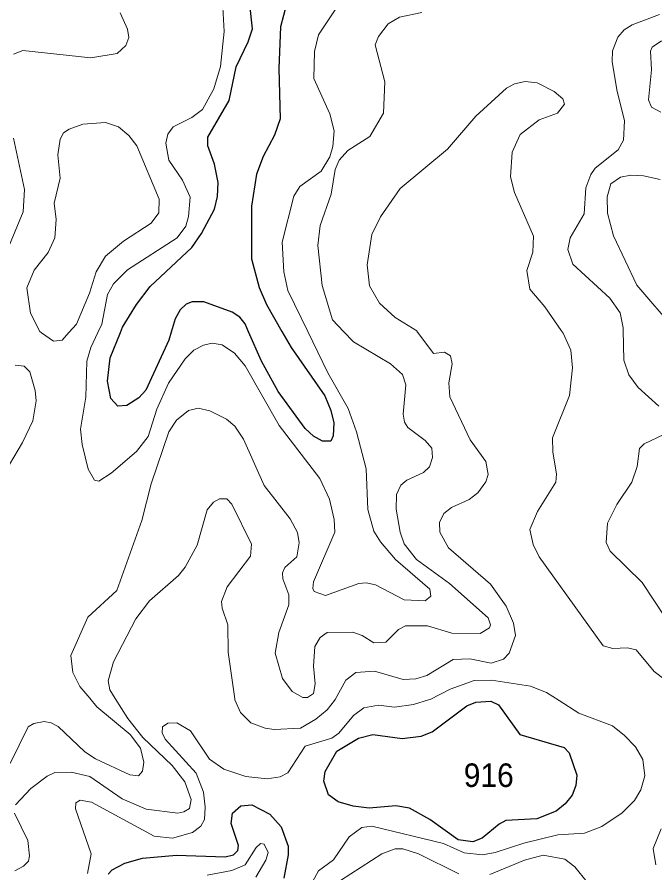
# Model space of a CAD drawing. Extents: x 473.9 to 500, y 7733.1 to 7760.8.
# Drawn here: x 490.401 to 492.567, y 7740.495 to 7743.401 of the extents above; entities that cross this region are included whole.
import ezdxf

# ---------------------------------------------------------------- set-up
doc = ezdxf.new("R2010")
doc.units = 0
doc.header["$LTSCALE"] = 0.032
doc.layers.add('1', color=7, linetype='Continuous', lineweight=25)
doc.layers.add('2', color=7, linetype='Continuous', lineweight=13)
doc.layers.add('21', color=7, linetype='Continuous')

msp = doc.modelspace()

# ---------------------------------------------------------------- linework, layer by layer
at = {"layer": '1'}
for points in [[(491.3263, 7743.4848), (491.2954, 7743.3689), (491.2906, 7743.2268), (491.2949, 7743.0556), (491.2755, 7743.0003), (491.2369, 7742.9279), (491.2146, 7742.8682), (491.1973, 7742.7591), (491.1972, 7742.5807), (491.2232, 7742.483), (491.2488, 7742.4256), (491.3009, 7742.3333), (491.3316, 7742.2789), (491.4465, 7742.1152), (491.467, 7742.0658), (491.477, 7742.0236), (491.4748, 7741.9793), (491.4673, 7741.9618), (491.4385, 7741.9609), (491.4077, 7741.9782), (491.3794, 7742.0048), (491.2881, 7742.1302), (491.2313, 7742.2335), (491.1874, 7742.3328), (491.1756, 7742.3594), (491.1581, 7742.3824), (491.1313, 7742.3998), (491.0358, 7742.4345), (490.996, 7742.4343), (490.976, 7742.4264), (490.9552, 7742.4078), (490.9378, 7742.3763), (490.9244, 7742.3316), (490.9161, 7742.304), (490.8389, 7742.1344), (490.815, 7742.1085), (490.7739, 7742.082), (490.7435, 7742.08), (490.7197, 7742.1057), (490.7086, 7742.1648), (490.7169, 7742.2443), (490.7526, 7742.3308), (490.7597, 7742.348), (490.8064, 7742.4251), (490.8527, 7742.4862), (490.995, 7742.6191), (491.028, 7742.6666), (491.0712, 7742.7494), (491.0822, 7742.7922), (491.0837, 7742.8401), (491.0718, 7742.9016), (491.0494, 7742.9644), (491.0487, 7742.9932), (491.1216, 7743.1186), (491.145, 7743.2324), (491.1862, 7743.317), (491.2005, 7743.3612), (491.1917, 7743.4447)], [(490.7106, 7740.4911), (490.7246, 7740.5056), (490.7669, 7740.5284), (490.8274, 7740.545), (490.9432, 7740.5554), (491.1078, 7740.5499), (491.1357, 7740.556), (491.1508, 7740.5708), (491.1531, 7740.5886), (491.1278, 7740.6627), (491.1331, 7740.6978), (491.1616, 7740.7231), (491.1982, 7740.726), (491.2594, 7740.6941), (491.2981, 7740.6514), (491.3218, 7740.586), (491.3219, 7740.5567), (491.3075, 7740.4772)]]:
    msp.add_lwpolyline(points, dxfattribs=at)
msp.add_lwpolyline([(491.4583, 7740.7605), (491.4433, 7740.8069), (491.4472, 7740.8395), (491.4871, 7740.9086), (491.5606, 7740.9526), (491.6089, 7740.9647), (491.7086, 7740.9511), (491.7741, 7740.9592), (491.8107, 7740.9744), (491.929, 7741.0627), (491.9589, 7741.0754), (492.0098, 7741.0789), (492.0363, 7741.0665), (492.1085, 7740.965), (492.2595, 7740.9206), (492.2766, 7740.9024), (492.3019, 7740.8266), (492.2988, 7740.7924), (492.2862, 7740.7592), (492.2629, 7740.7296), (492.2318, 7740.7046), (492.1669, 7740.6793), (492.0612, 7740.6731), (492.0381, 7740.6609), (491.9811, 7740.6134), (491.9492, 7740.6005), (491.8997, 7740.6079), (491.8031, 7740.6768), (491.7337, 7740.7147), (491.6874, 7740.7227), (491.5968, 7740.7146), (491.5427, 7740.7216), (491.4921, 7740.7362)], close=True, dxfattribs=at)
at = {"layer": '2'}
for points in [[(491.5621, 7741.4778), (491.587, 7741.4808), (491.618, 7741.4739), (491.716, 7741.4226), (491.7869, 7741.4187), (491.8069, 7741.4348), (491.8033, 7741.4582), (491.6862, 7741.5597), (491.6353, 7741.6195), (491.6127, 7741.656), (491.5922, 7741.7288), (491.5867, 7741.8669), (491.5538, 7741.9935), (491.5258, 7742.0723), (491.4563, 7742.1939), (491.3885, 7742.3337), (491.321, 7742.4728), (491.307, 7742.5364), (491.3019, 7742.6374), (491.3408, 7742.7934), (491.3615, 7742.826), (491.434, 7742.8787), (491.4634, 7742.9274), (491.474, 7742.9623), (491.478, 7743.0155), (491.4628, 7743.0724), (491.4095, 7743.1932), (491.411, 7743.2847), (491.4245, 7743.341), (491.5397, 7743.5144)], [(491.0984, 7743.4542), (491.1049, 7743.3529), (491.0917, 7743.2333), (491.0694, 7743.1573), (491.0309, 7743.088), (490.9952, 7743.0602), (490.9311, 7743.0286), (490.9132, 7743.004), (490.9063, 7742.9734), (490.9169, 7742.9155), (490.9627, 7742.848), (490.9896, 7742.7896), (490.9834, 7742.7248), (490.9739, 7742.6915), (490.9448, 7742.6516), (490.7768, 7742.5437), (490.729, 7742.4954), (490.7086, 7742.459), (490.6893, 7742.3586), (490.6759, 7742.3304), (490.6515, 7742.2789), (490.6381, 7742.2328), (490.635, 7742.1109), (490.6167, 7742.0016), (490.622, 7741.9495), (490.6427, 7741.8661), (490.6647, 7741.8288), (490.6794, 7741.8252), (490.7204, 7741.8524), (490.8068, 7741.9268), (490.8466, 7741.977), (490.8758, 7742.0701), (490.9151, 7742.1587), (490.9723, 7742.2413), (491.002, 7742.2703), (491.0343, 7742.2879), (491.0638, 7742.2937), (491.0976, 7742.2888), (491.1393, 7742.2607), (491.1759, 7742.2168), (491.2908, 7742.0143), (491.4292, 7741.8341), (491.4617, 7741.7647), (491.4781, 7741.6953), (491.4802, 7741.6522), (491.408, 7741.4833), (491.4056, 7741.4605), (491.4107, 7741.4511), (491.4485, 7741.4376), (491.5621, 7741.4778)], [(490.3895, 7743.2758), (490.4212, 7743.2883), (490.6516, 7743.2627), (490.7411, 7743.2782), (490.7704, 7743.3051), (490.7806, 7743.3324), (490.7765, 7743.3604), (490.7513, 7743.4156)], [(491.6531, 7741.2789), (491.6969, 7741.3221), (491.7206, 7741.3341), (491.7945, 7741.3345), (491.8776, 7741.3095), (491.9739, 7741.3081), (492.0055, 7741.3272), (492.0092, 7741.3371), (492.0012, 7741.3619), (491.8701, 7741.4776), (491.7576, 7741.5594), (491.7153, 7741.613), (491.7021, 7741.6527), (491.6884, 7741.7305), (491.6894, 7741.7804), (491.7043, 7741.8121), (491.7243, 7741.8294), (491.7812, 7741.8547), (491.8015, 7741.8742), (491.8125, 7741.9062), (491.8099, 7741.9374), (491.7874, 7741.9641), (491.7284, 7742.0078), (491.7169, 7742.0257), (491.7119, 7742.0531), (491.7213, 7742.1532), (491.7096, 7742.1878), (491.6693, 7742.2234), (491.5435, 7742.2985), (491.5096, 7742.3342), (491.4728, 7742.3731), (491.437, 7742.4904), (491.4224, 7742.6255), (491.4311, 7742.6936), (491.4682, 7742.8003), (491.4818, 7742.8834), (491.4948, 7742.916), (491.5241, 7742.9486), (491.5996, 7742.996), (491.6461, 7743.075), (491.6507, 7743.1814), (491.6178, 7743.3073), (491.6284, 7743.3356), (491.6612, 7743.3791), (491.6995, 7743.4009), (491.7762, 7743.4169)], [(492.5829, 7743.4103), (492.4896, 7743.3757), (492.4628, 7743.3582), (492.4414, 7743.3331), (492.4228, 7743.2864), (492.4226, 7743.251), (492.4382, 7743.1539), (492.4643, 7743.0495), (492.4609, 7742.9831), (492.4424, 7742.9504), (492.364, 7742.8886), (492.3494, 7742.8672), (492.3328, 7742.8214), (492.3275, 7742.7338), (492.2792, 7742.6518), (492.2715, 7742.6121), (492.2886, 7742.5624), (492.4141, 7742.447), (492.4496, 7742.3966), (492.4595, 7742.3457), (492.4596, 7742.3386), (492.4617, 7742.2366), (492.4787, 7742.1866), (492.5103, 7742.144), (492.5809, 7742.0806)], [(492.5899, 7743.3212), (492.5582, 7743.2999), (492.5529, 7743.2863), (492.5561, 7743.2222), (492.5456, 7743.1209), (492.5552, 7743.0955), (492.5869, 7743.0781)], [(492.1542, 7741.6104), (492.1428, 7741.6609), (492.1685, 7741.7229), (492.2308, 7741.8223), (492.2336, 7741.8489), (492.2206, 7741.9251), (492.22, 7741.9727), (492.2778, 7742.1169), (492.2876, 7742.2101), (492.2813, 7742.2701), (492.2559, 7742.3281), (492.2492, 7742.3376), (492.1937, 7742.417), (492.1427, 7742.4776), (492.1324, 7742.5409), (492.1526, 7742.6036), (492.1548, 7742.6571), (492.0906, 7742.8056), (492.0769, 7742.8587), (492.0821, 7742.9433), (492.1092, 7743.0028), (492.1738, 7743.053), (492.2364, 7743.0756), (492.2605, 7743.1059), (492.2545, 7743.1235), (492.2249, 7743.1493), (492.1674, 7743.1787), (492.1267, 7743.183), (492.0908, 7743.1744), (492.0628, 7743.16), (491.9587, 7743.0648), (491.8631, 7742.9531), (491.7017, 7742.8191), (491.6351, 7742.7233), (491.6055, 7742.6631), (491.5905, 7742.5602), (491.5978, 7742.4884), (491.6323, 7742.4303), (491.6857, 7742.3817), (491.7584, 7742.3363), (491.7591, 7742.3354), (491.815, 7742.2587), (491.8528, 7742.264), (491.8729, 7742.2509), (491.8789, 7742.2245), (491.8671, 7742.1598), (491.8707, 7742.1115), (491.9402, 7741.9658), (491.9929, 7741.8923), (492.0012, 7741.8483), (491.9932, 7741.8227), (491.9659, 7741.7857), (491.9365, 7741.7629), (491.8763, 7741.736), (491.8506, 7741.716), (491.8359, 7741.6853), (491.8364, 7741.6526), (491.8666, 7741.599), (492.0089, 7741.4756), (492.0625, 7741.4008), (492.0873, 7741.3434), (492.0936, 7741.3018), (492.0727, 7741.2416), (492.053, 7741.2207), (492.0109, 7741.2076), (491.9391, 7741.2219), (491.8824, 7741.2204), (491.7933, 7741.1655), (491.7558, 7741.1537), (491.7129, 7741.1519), (491.6148, 7741.1803), (491.5511, 7741.1753), (491.5177, 7741.1499), (491.4811, 7741.0842), (491.4789, 7741.0802), (491.4539, 7741.0484), (491.4156, 7741.0173), (491.3639, 7740.9869), (491.2744, 7740.9825), (491.2434, 7740.987), (491.195, 7741.0052), (491.1603, 7741.0395), (491.1407, 7741.0824), (491.1402, 7741.0858), (491.1185, 7741.2453), (491.1169, 7741.3381), (491.0978, 7741.3938), (491.0959, 7741.4163), (491.1145, 7741.4672), (491.1937, 7741.5712), (491.1974, 7741.6118), (491.1309, 7741.7475), (491.1135, 7741.7652), (491.089, 7741.7653), (491.0679, 7741.7547), (491.0463, 7741.7276), (491.0126, 7741.6077), (490.972, 7741.5338), (490.9489, 7741.5051), (490.851, 7741.4192)], [(490.3541, 7742.5756), (490.4215, 7742.7398), (490.4263, 7742.8158), (490.3888, 7742.9905)], [(492.5855, 7742.8497), (492.5285, 7742.8625), (492.4853, 7742.8646), (492.4504, 7742.8576), (492.418, 7742.8354), (492.4048, 7742.791), (492.4066, 7742.736), (492.4272, 7742.6583), (492.5059, 7742.4916), (492.6358, 7742.3394)], [(490.3953, 7742.2193), (490.4253, 7742.2156), (490.4445, 7742.197), (490.463, 7742.1334), (490.4665, 7742.0981), (490.4542, 7742.03), (490.42, 7741.9565), (490.3753, 7741.8816)], [(490.3774, 7740.8672), (490.4394, 7740.9908), (490.4577, 7741.0021), (490.4929, 7741.0089), (490.517, 7741.0049), (490.5408, 7740.9924), (490.6318, 7740.9061), (490.6677, 7740.8822), (490.7845, 7740.8281), (490.8133, 7740.8251), (490.8274, 7740.8405), (490.8322, 7740.8717), (490.8209, 7740.9189), (490.7849, 7740.9647), (490.6726, 7741.0591), (490.6484, 7741.0881), (490.6148, 7741.1284), (490.5903, 7741.1761), (490.5838, 7741.2339), (490.641, 7741.364), (490.7395, 7741.4544), (490.8248, 7741.6918), (490.8564, 7741.8161), (490.9163, 7741.9936), (490.9424, 7742.0332), (490.9831, 7742.0652), (491.0161, 7742.0735), (491.0557, 7742.0646), (491.113, 7742.0358), (491.1405, 7742.0119), (491.1701, 7741.9684), (491.2401, 7741.8109), (491.3283, 7741.6971), (491.353, 7741.6511), (491.3597, 7741.6157), (491.3509, 7741.5691), (491.311, 7741.5322), (491.3028, 7741.5139), (491.3032, 7741.4935), (491.3238, 7741.4393), (491.3243, 7741.4051), (491.2906, 7741.3112), (491.2777, 7741.2416), (491.3022, 7741.1558), (491.3355, 7741.1117), (491.3714, 7741.0905), (491.3873, 7741.0904), (491.4077, 7741.1049), (491.4135, 7741.1372), (491.4079, 7741.1972), (491.4124, 7741.2645), (491.4305, 7741.2951), (491.4545, 7741.3112), (491.5418, 7741.3131), (491.573, 7741.3018), (491.6128, 7741.2764), (491.6531, 7741.2789)], [(492.5971, 7741.9835), (492.5303, 7741.9521), (492.5145, 7741.9363), (492.5066, 7741.8755), (492.489, 7741.8223), (492.4381, 7741.746), (492.4059, 7741.6829), (492.4023, 7741.6171), (492.4152, 7741.588), (492.5245, 7741.4815), (492.601, 7741.365)], [(492.602, 7741.1507), (492.5645, 7741.179), (492.5035, 7741.2531), (492.4746, 7741.2596), (492.4247, 7741.2567), (492.3918, 7741.2658), (492.1739, 7741.5683), (492.1542, 7741.6104)], [(490.851, 7741.4192), (490.8045, 7741.3584), (490.7289, 7741.2121), (490.7107, 7741.1477), (490.7159, 7741.1165), (490.7341, 7741.0877), (490.7771, 7741.0194), (490.8281, 7740.9546), (490.9278, 7740.8596), (490.9713, 7740.8039), (490.9922, 7740.7447), (490.9866, 7740.7143), (490.9679, 7740.7021), (490.9469, 7740.6977), (490.8397, 7740.712), (490.7577, 7740.7471), (490.6484, 7740.8224), (490.5846, 7740.837), (490.5294, 7740.8358), (490.5033, 7740.8234), (490.4476, 7740.7817), (490.3959, 7740.7263)], [(491.5442, 7741.0302), (491.5789, 7741.0553), (491.6282, 7741.0643), (491.6834, 7741.0579), (491.747, 7741.0667), (491.7984, 7741.0828), (491.8036, 7741.0844), (491.8724, 7741.1191), (491.9536, 7741.1481), (492.012, 7741.1494), (492.1444, 7741.1295), (492.1995, 7741.1078), (492.2417, 7741.0807), (492.309, 7741.0375), (492.4232, 7740.9942), (492.4646, 7740.9623), (492.5013, 7740.9237), (492.5263, 7740.8803), (492.5335, 7740.8246), (492.5191, 7740.7778), (492.4977, 7740.7416), (492.4563, 7740.6994), (492.3867, 7740.6524), (492.3284, 7740.6304), (492.2382, 7740.624), (492.1219, 7740.5964), (492.0248, 7740.5642), (491.9815, 7740.5571), (491.9193, 7740.5639), (491.849, 7740.5952), (491.606, 7740.6534), (491.5715, 7740.6497), (491.5286, 7740.6182), (491.4755, 7740.5395), (491.4247, 7740.5026), (491.4048, 7740.4645)], [(490.6399, 7740.4929), (490.6527, 7740.5598), (490.6002, 7740.7129), (490.6004, 7740.7326), (490.6154, 7740.7422), (490.6543, 7740.7352), (490.8671, 7740.6195), (490.9293, 7740.613), (490.9972, 7740.6324), (491.0248, 7740.654), (491.0375, 7740.6771), (491.0405, 7740.7179), (491.0348, 7740.7693), (491.0099, 7740.8336), (490.9047, 7740.9495), (490.8944, 7740.9711), (490.8946, 7740.9908), (490.9137, 7741.0039), (490.9437, 7741.0047), (490.9898, 7740.9775), (491.0542, 7740.8812), (491.1035, 7740.8476), (491.1778, 7740.8228), (491.2503, 7740.8151), (491.2943, 7740.8214), (491.321, 7740.8345), (491.3796, 7740.9259), (491.4698, 7740.9524), (491.4935, 7740.97), (491.5442, 7741.0302)], [(490.3922, 7740.6982), (490.4376, 7740.6048), (490.4437, 7740.5527), (490.4398, 7740.5354), (490.4229, 7740.5176), (490.3937, 7740.5019)], [(492.5703, 7740.5228), (492.5617, 7740.5775), (492.5881, 7740.645)], [(491.0472, 7740.488), (491.1308, 7740.5031), (491.1755, 7740.5226), (491.2137, 7740.5817), (491.2284, 7740.5948), (491.2403, 7740.5925), (491.2542, 7740.565), (491.246, 7740.5389), (491.212, 7740.4807)], [(491.4995, 7740.4689), (491.6403, 7740.5598), (491.6848, 7740.5764), (491.7109, 7740.5766), (491.765, 7740.5602), (491.901, 7740.4917)], [(492.007, 7740.4898), (492.1246, 7740.5389), (492.1878, 7740.5553), (492.2618, 7740.5418), (492.2956, 7740.5159), (492.3371, 7740.4638)]]:
    msp.add_lwpolyline(points, dxfattribs=at)
msp.add_lwpolyline([(490.8568, 7742.7018), (490.8825, 7742.737), (490.8841, 7742.7827), (490.8075, 7742.9638), (490.7803, 7742.9993), (490.7462, 7743.0285), (490.7015, 7743.0439), (490.6248, 7743.0374), (490.5776, 7743.021), (490.5594, 7743.0082), (490.5474, 7742.9874), (490.5396, 7742.9332), (490.5476, 7742.8544), (490.5277, 7742.7692), (490.534, 7742.7139), (490.5289, 7742.6518), (490.5067, 7742.6016), (490.4596, 7742.542), (490.4344, 7742.4825), (490.4466, 7742.3961), (490.478, 7742.3343), (490.4847, 7742.3296), (490.5246, 7742.3011), (490.5543, 7742.3043), (490.5774, 7742.33), (490.6036, 7742.3591), (490.6471, 7742.4637), (490.6695, 7742.5359), (490.7013, 7742.5893), (490.7622, 7742.6404)], close=True, dxfattribs=at)

# ---------------------------------------------------------------- texts
at = {"layer": '21', "width": 0.95}
msp.add_text('916', height=0.08, dxfattribs=at).set_placement((491.9182, 7740.787))

doc.saveas('drawing.dxf')
